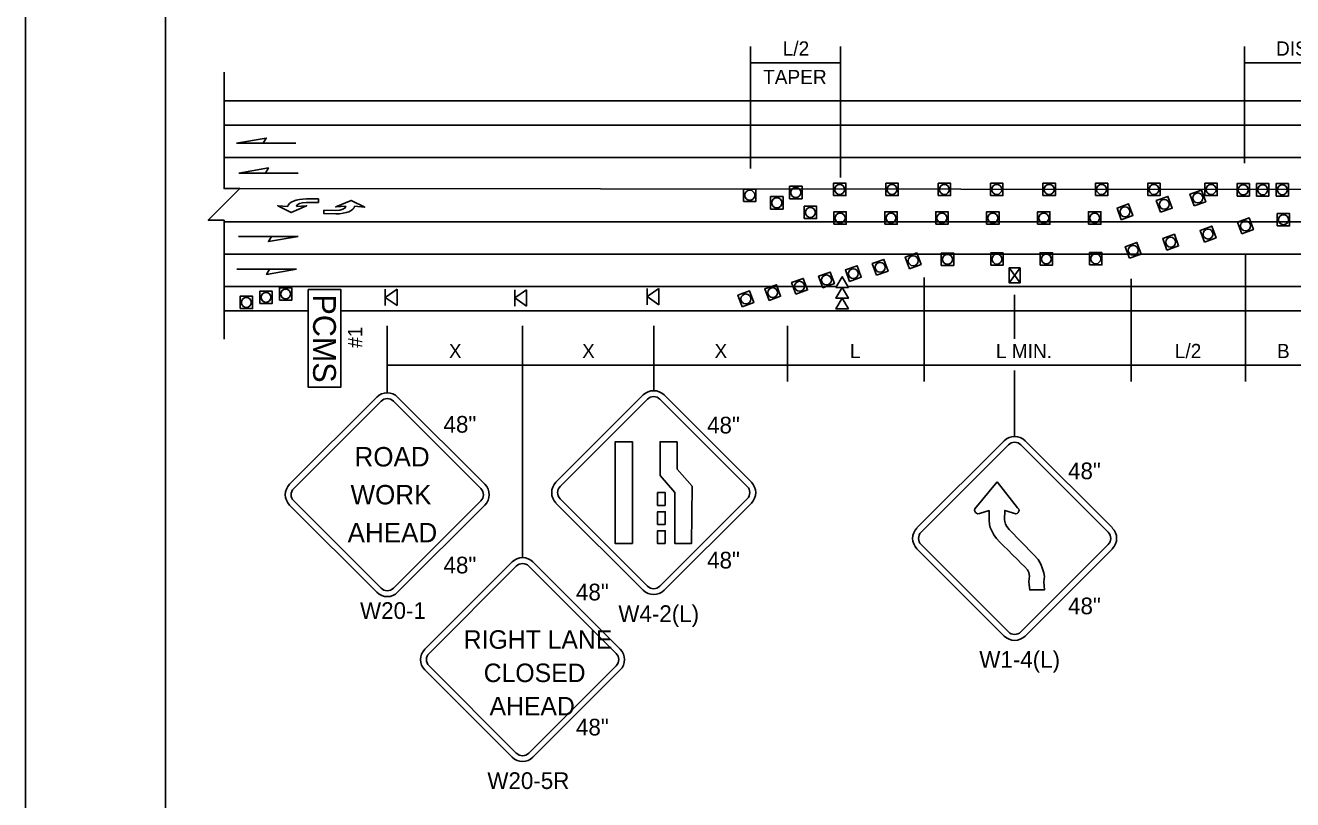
# Model space of a CAD drawing. Extents: x 99988 to 100172, y 99995 to 100047.
# Drawn here: x 99999.31 to 100005.53, y 100002.93 to 100006.73 of the extents above; entities that cross this region are included whole.
import ezdxf

# ---------------------------------------------------------------- set-up
doc = ezdxf.new("R2010")
doc.units = 0
for name, color, linetype in [('Default', 7, 'Continuous'), ('Level 15', 7, 'Continuous'), ('Level 20', 7, 'Continuous'), ('RD_MK_TrafficArrowType2LNew', 7, 'Continuous'), ('SH_GI_PlotLimits', 7, 'Continuous'), ('SH_GI_SheetBorder', 7, 'Continuous'), ('SH_GI_TrafficMvmntArrowRt1Lane', 7, 'Continuous'), ('TR_SN_WarningSigns', 7, 'Continuous'), ('TR_WZ_PortableChangeMessageSign', 7, 'Continuous'), ('TR_WZ_TrafficSafetyCone', 7, 'Continuous'), ('TR_WZ_WorkZoneDetails', 7, 'Continuous')]:
    doc.layers.add(name, color=color, linetype=linetype)

msp = doc.modelspace()

# ---------------------------------------------------------------- linework, layer by layer
at = {"layer": 'Default'}
for p, q in [((100000.2851, 100006.0802), (100006.7403, 100006.0802)), ((100010.7948, 100005.918), (100000.3647, 100005.9267)), ((100000.2916, 100005.7634), (100010.9542, 100005.7634)), ((100000.2873, 100005.6051), (100006.1821, 100005.6051)), ((100004.1939, 100005.5373), (100004.1395, 100005.4647)), ((100004.1395, 100005.5373), (100004.1939, 100005.4647)), ((100004.1667, 100005.501), (100004.1667, 100005.501)), ((100004.1668, 100005.5011), (100004.1668, 100005.5011)), ((100001.1362, 100005.433), (100001.0784, 100005.3927)), ((100001.0784, 100005.3525), (100001.0784, 100005.433)), ((100001.1362, 100005.3525), (100001.1362, 100005.433)), ((100001.7713, 100005.4308), (100001.7135, 100005.3905)), ((100001.7135, 100005.3504), (100001.7135, 100005.4308)), ((100001.7713, 100005.3504), (100001.7713, 100005.4308)), ((100002.4215, 100005.4373), (100002.3638, 100005.397)), ((100002.3638, 100005.3569), (100002.3638, 100005.4373)), ((100002.4215, 100005.3569), (100002.3638, 100005.397)), ((100002.4215, 100005.3569), (100002.4215, 100005.4373)), ((100001.1362, 100005.3525), (100001.0784, 100005.3927)), ((100001.7713, 100005.3504), (100001.7135, 100005.3905))]:
    msp.add_line(p, q, dxfattribs=at)
msp.add_lwpolyline([(100004.1939, 100005.5373), (100004.1395, 100005.5373), (100004.1395, 100005.4647), (100004.1939, 100005.4647)], close=True, dxfattribs=at)
at = {"layer": 'Level 15'}
for p, q in [((100002.8711, 100006.5446), (100003.0914, 100006.5446)), ((100003.3116, 100006.5446), (100003.0914, 100006.5446)), ((100005.295, 100006.5446), (100006.1066, 100006.5446)), ((100001.0883, 100005.0597), (100001.4203, 100005.0597)), ((100001.7522, 100005.0597), (100001.4203, 100005.0597)), ((100001.7522, 100005.0597), (100002.0739, 100005.0597)), ((100002.3955, 100005.0597), (100002.0739, 100005.0597)), ((100002.3955, 100005.0597), (100002.7237, 100005.0597)), ((100003.0518, 100005.0597), (100002.7237, 100005.0597)), ((100003.0518, 100005.0597), (100003.3873, 100005.0597)), ((100003.7229, 100005.0597), (100003.3873, 100005.0597)), ((100003.7229, 100005.0597), (100004.231, 100005.0597)), ((100004.739, 100005.0597), (100004.231, 100005.0597)), ((100004.739, 100005.0597), (100005.0192, 100005.0597)), ((100005.2994, 100005.0597), (100005.0192, 100005.0597)), ((100005.2994, 100005.0597), (100005.4876, 100005.0597)), ((100005.6757, 100005.0597), (100005.4876, 100005.0597))]:
    msp.add_line(p, q, dxfattribs=at)
at = {"layer": 'RD_MK_TrafficArrowType2LNew'}
for p, q in [((100000.6009, 100005.8387), (100000.6009, 100005.8387)), ((100000.6426, 100005.8387), (100000.6426, 100005.8387)), ((100000.6926, 100005.8762), (100000.6926, 100005.8762)), ((100000.6926, 100005.8762), (100000.6926, 100005.8762)), ((100000.6926, 100005.8595), (100000.6926, 100005.8595)), ((100000.8858, 100005.8403), (100000.8858, 100005.8403)), ((100000.9275, 100005.8399), (100000.9275, 100005.8399)), ((100000.8355, 100005.8034), (100000.8355, 100005.8034)), ((100000.8355, 100005.8034), (100000.8355, 100005.8034)), ((100000.8356, 100005.82), (100000.8356, 100005.82))]:
    msp.add_line(p, q, dxfattribs=at)
for points in [[(100000.6426, 100005.8387), (100000.6926, 100005.8429), (100000.6176, 100005.8095), (100000.5509, 100005.8429), (100000.6009, 100005.8387)], [(100000.6926, 100005.8762), (100000.7509, 100005.8762), (100000.7509, 100005.8595), (100000.6926, 100005.8595)], [(100000.8858, 100005.8403), (100000.8358, 100005.8367), (100000.9111, 100005.8693), (100000.9775, 100005.8353), (100000.9275, 100005.8399)], [(100000.8355, 100005.8034), (100000.7771, 100005.804), (100000.7773, 100005.8206), (100000.8356, 100005.82)]]:
    msp.add_lwpolyline(points, dxfattribs=at)
for centre, major_axis, ratio, start_param in [((100000.6926, 100005.8387), (-0.0917, 0), 0.40879, 4.712524), ((100000.6926, 100005.8387), (-0.05, 0), 0.41611, 4.712518), ((100000.8358, 100005.8408), (0.0917, -0.0009), 0.40879, 4.712524), ((100000.8358, 100005.8408), (0.05, -0.0005), 0.41611, 4.712518)]:
    msp.add_ellipse(centre, major_axis=major_axis, ratio=ratio, start_param=start_param, end_param=6.283185, dxfattribs=at)
at = {"layer": 'SH_GI_PlotLimits'}
msp.add_lwpolyline([(99999.3125, 99999.9375), (100015.8125, 99999.9375), (100015.8125, 100010.4375), (99999.3125, 100010.4375)], close=True, dxfattribs=at)
at = {"layer": 'SH_GI_SheetBorder'}
msp.add_line((100000, 100010.375), (100000, 100000), dxfattribs=at)
at = {"layer": 'SH_GI_TrafficMvmntArrowRt1Lane'}
for p, q in [((100000.4795, 100006.1493), (100000.6403, 100006.1493)), ((100000.4904, 100006.0023), (100000.6512, 100006.0023)), ((100000.5196, 100005.6923), (100000.3589, 100005.6923)), ((100000.5113, 100005.5312), (100000.3505, 100005.5312))]:
    msp.add_line(p, q, dxfattribs=at)
for points in [[(100000.3485, 100006.1493), (100000.4944, 100006.175), (100000.4795, 100006.1493)], [(100000.3594, 100006.0023), (100000.5053, 100006.0281), (100000.4904, 100006.0023)], [(100000.6507, 100005.6923), (100000.5048, 100005.6666), (100000.5196, 100005.6923)], [(100000.6423, 100005.5312), (100000.4964, 100005.5055), (100000.5113, 100005.5312)]]:
    msp.add_lwpolyline(points, close=True, dxfattribs=at)
at = {"layer": 'TR_SN_WarningSigns'}
for p, q in [((100000.609, 100004.4754), (100001.0373, 100004.9038)), ((100001.1393, 100004.9038), (100001.5676, 100004.4754)), ((100001.9162, 100004.4855), (100002.3445, 100004.9139)), ((100002.4465, 100004.9139), (100002.8749, 100004.4855)), ((100000.6294, 100004.455), (100001.0577, 100004.8834)), ((100001.1189, 100004.8834), (100001.5473, 100004.455)), ((100001.9366, 100004.4651), (100002.3649, 100004.8935)), ((100002.4261, 100004.8935), (100002.8545, 100004.4651)), ((100004.1156, 100004.6892), (100003.6873, 100004.2609)), ((100004.136, 100004.6688), (100003.7077, 100004.2405)), ((100004.6256, 100004.2405), (100004.1972, 100004.6688)), ((100004.646, 100004.2609), (100004.2176, 100004.6892)), ((100002.3649, 100003.9756), (100001.9366, 100004.404)), ((100002.8545, 100004.404), (100002.4261, 100003.9756)), ((100001.0373, 100003.9451), (100000.609, 100004.3734)), ((100001.0577, 100003.9655), (100000.6294, 100004.3938)), ((100001.5472, 100004.3938), (100001.1189, 100003.9655)), ((100001.5676, 100004.3734), (100001.1393, 100003.9451)), ((100002.3445, 100003.9552), (100001.9162, 100004.3836)), ((100002.8749, 100004.3836), (100002.4465, 100003.9552)), ((100003.6873, 100004.1589), (100004.1156, 100003.7306)), ((100003.7077, 100004.1793), (100004.136, 100003.7509)), ((100004.1972, 100003.7509), (100004.6256, 100004.1793)), ((100004.2176, 100003.7306), (100004.646, 100004.1589)), ((100001.2729, 100003.6659), (100001.7012, 100004.0943)), ((100001.8032, 100004.0943), (100002.2315, 100003.6659)), ((100001.2933, 100003.6455), (100001.7216, 100004.0739)), ((100001.7828, 100004.0739), (100002.2112, 100003.6455)), ((100001.7012, 100003.1356), (100001.2729, 100003.5639)), ((100001.7216, 100003.156), (100001.2933, 100003.5844)), ((100002.2112, 100003.5844), (100001.7828, 100003.156)), ((100002.2315, 100003.5639), (100001.8032, 100003.1356))]:
    msp.add_line(p, q, dxfattribs=at)
for points in [[(100002.291, 100004.1846), (100002.2071, 100004.1846), (100002.2071, 100004.6846), (100002.291, 100004.6846)], [(100002.511, 100004.6845), (100002.511, 100004.5497), (100002.584, 100004.4661), (100002.5804, 100004.1845), (100002.5, 100004.1845), (100002.5, 100004.4346), (100002.427, 100004.5182), (100002.427, 100004.6845)], [(100004.0816, 100004.4868), (100003.9709, 100004.3554), (100003.9692, 100004.3476), (100003.974, 100004.3378), (100003.9843, 100004.3305), (100003.9935, 100004.3327), (100004.0416, 100004.3467), (100004.042, 100004.299), (100004.0435, 100004.2773), (100004.0469, 100004.2634), (100004.0525, 100004.2501), (100004.0653, 100004.2275), (100004.0781, 100004.2097), (100004.0935, 100004.1914), (100004.1124, 100004.1739), (100004.1333, 100004.1532), (100004.1562, 100004.1293), (100004.1785, 100004.1077), (100004.1982, 100004.0867), (100004.2154, 100004.0712), (100004.2291, 100004.0549), (100004.2359, 100004.0419), (100004.2389, 100004.0242), (100004.2366, 100003.998), (100004.2382, 100003.9812), (100004.2405, 100003.9572), (100004.3124, 100003.9573), (100004.3102, 100003.9973), (100004.3125, 100004.0235), (100004.3095, 100004.0412), (100004.3036, 100004.0606), (100004.2957, 100004.0832), (100004.2827, 100004.107), (100004.2586, 100004.1306), (100004.1397, 100004.2539), (100004.1277, 100004.2682), (100004.1215, 100004.2789), (100004.1193, 100004.2931), (100004.1171, 100004.3023), (100004.1181, 100004.3475), (100004.1719, 100004.3305), (100004.1786, 100004.3318), (100004.1835, 100004.3366), (100004.1882, 100004.3476), (100004.1868, 100004.3534), (100004.1805, 100004.3592)], [(100002.4521, 100004.3721), (100002.415, 100004.3721), (100002.415, 100004.4346), (100002.4521, 100004.4346)], [(100002.4521, 100004.2783), (100002.415, 100004.2783), (100002.415, 100004.3408), (100002.4521, 100004.3408)], [(100002.4521, 100004.1846), (100002.415, 100004.1846), (100002.415, 100004.2471), (100002.4521, 100004.2471)]]:
    msp.add_lwpolyline(points, close=True, dxfattribs=at)
for centre, radius, start, end in [((100001.0883, 100004.8528), 0.0721, 44.99628, 134.99965), ((100002.3955, 100004.8629), 0.0721, 44.99628, 134.99965), ((100002.3955, 100004.8629), 0.0433, 44.99628, 134.99965), ((100001.0883, 100004.8528), 0.0433, 44.99628, 134.99965), ((100004.1666, 100004.6382), 0.0721, 44.99628, 134.99965), ((100004.1667, 100004.6382), 0.0433, 44.99628, 134.99965), ((100000.66, 100004.4244), 0.0721, 134.99658, 224.99358), ((100001.5167, 100004.4244), 0.0721, 314.99936, 44.99485), ((100001.9672, 100004.4346), 0.0721, 134.99658, 224.99358), ((100001.9672, 100004.4346), 0.0433, 134.99658, 224.99358), ((100002.8239, 100004.4345), 0.0433, 314.99936, 44.99485), ((100002.8239, 100004.4345), 0.0721, 314.99936, 44.99485), ((100000.66, 100004.4244), 0.0433, 134.99658, 224.99358), ((100001.5167, 100004.4244), 0.0433, 314.99936, 44.99485), ((100003.7383, 100004.2099), 0.0721, 134.99658, 224.99358), ((100003.7383, 100004.2099), 0.0433, 134.99658, 224.99358), ((100004.595, 100004.2099), 0.0433, 314.99936, 44.99485), ((100004.595, 100004.2099), 0.0721, 314.99936, 44.99485), ((100001.7522, 100004.0433), 0.0721, 44.99628, 134.99965), ((100001.7522, 100004.0433), 0.0433, 44.99628, 134.99965), ((100001.0883, 100003.9961), 0.0433, 225, 314.99958), ((100002.3955, 100004.0062), 0.0433, 225, 314.99958), ((100001.0883, 100003.9961), 0.0721, 225, 314.99958), ((100002.3955, 100004.0062), 0.0721, 225, 314.99958), ((100004.1666, 100003.7815), 0.0721, 225, 314.99958), ((100004.1666, 100003.7815), 0.0433, 225, 314.99958), ((100001.3239, 100003.6149), 0.0721, 134.99658, 224.99358), ((100002.1806, 100003.6149), 0.0721, 314.99936, 44.99485), ((100001.3239, 100003.6149), 0.0433, 134.99658, 224.99358), ((100002.1806, 100003.6149), 0.0433, 314.99936, 44.99485), ((100001.7522, 100003.1866), 0.0721, 225, 314.99958), ((100001.7522, 100003.1866), 0.0433, 225, 314.99958)]:
    msp.add_arc(centre, radius, start, end, dxfattribs=at)
at = {"layer": 'TR_WZ_PortableChangeMessageSign'}
msp.add_lwpolyline([(100000.7004, 100005.4317), (100000.7004, 100004.9517), (100000.8604, 100004.9517), (100000.8604, 100005.4317)], close=True, dxfattribs=at)
at = {"layer": 'TR_WZ_TrafficSafetyCone'}
for points in [[(100002.8367, 100005.8642), (100002.8975, 100005.8642), (100002.8975, 100005.9249), (100002.8367, 100005.9249)], [(100003.0625, 100005.8775), (100003.1233, 100005.8775), (100003.1233, 100005.9382), (100003.0625, 100005.9382)], [(100003.2777, 100005.8923), (100003.3384, 100005.8923), (100003.3384, 100005.953), (100003.2777, 100005.953)], [(100003.5347, 100005.8923), (100003.5954, 100005.8923), (100003.5954, 100005.953), (100003.5347, 100005.953)], [(100003.7917, 100005.8923), (100003.8524, 100005.8923), (100003.8524, 100005.953), (100003.7917, 100005.953)], [(100004.0487, 100005.8923), (100004.1094, 100005.8923), (100004.1094, 100005.953), (100004.0487, 100005.953)], [(100004.3057, 100005.8923), (100004.3664, 100005.8923), (100004.3664, 100005.953), (100004.3057, 100005.953)], [(100004.5627, 100005.8923), (100004.6234, 100005.8923), (100004.6234, 100005.953), (100004.5627, 100005.953)], [(100004.8197, 100005.8923), (100004.8804, 100005.8923), (100004.8804, 100005.953), (100004.8197, 100005.953)], [(100005.0473, 100005.8421), (100005.1044, 100005.8628), (100005.0836, 100005.9199), (100005.0266, 100005.8991)], [(100005.1002, 100005.8923), (100005.161, 100005.8923), (100005.161, 100005.953), (100005.1002, 100005.953)], [(100005.2577, 100005.8905), (100005.3184, 100005.8905), (100005.3184, 100005.9513), (100005.2577, 100005.9513)], [(100005.3536, 100005.8906), (100005.4143, 100005.8906), (100005.4143, 100005.9513), (100005.3536, 100005.9513)], [(100005.4495, 100005.8906), (100005.5102, 100005.8906), (100005.5102, 100005.9514), (100005.4495, 100005.9514)], [(100002.9694, 100005.8267), (100003.0302, 100005.8267), (100003.0302, 100005.8874), (100002.9694, 100005.8874)], [(100003.134, 100005.7795), (100003.1948, 100005.7795), (100003.1948, 100005.8403), (100003.134, 100005.8403)], [(100004.6897, 100005.774), (100004.7468, 100005.7948), (100004.726, 100005.8518), (100004.669, 100005.8311)], [(100004.8826, 100005.8107), (100004.9397, 100005.8315), (100004.9189, 100005.8886), (100004.8618, 100005.8678)], [(100003.2798, 100005.7523), (100003.3405, 100005.7523), (100003.3405, 100005.813), (100003.2798, 100005.813)], [(100003.5296, 100005.7523), (100003.5904, 100005.7523), (100003.5904, 100005.813), (100003.5296, 100005.813)], [(100003.7795, 100005.7522), (100003.8402, 100005.7522), (100003.8402, 100005.813), (100003.7795, 100005.813)], [(100004.0293, 100005.7522), (100004.09, 100005.7522), (100004.09, 100005.8129), (100004.0293, 100005.8129)], [(100004.2791, 100005.7522), (100004.3398, 100005.7522), (100004.3398, 100005.8129), (100004.2791, 100005.8129)], [(100004.5289, 100005.7521), (100004.5897, 100005.7521), (100004.5897, 100005.8129), (100004.5289, 100005.8129)], [(100005.2814, 100005.7048), (100005.3385, 100005.7256), (100005.3177, 100005.7827), (100005.2606, 100005.7619)], [(100005.4554, 100005.7438), (100005.5161, 100005.7438), (100005.5161, 100005.8045), (100005.4554, 100005.8045)], [(100005.0977, 100005.6648), (100005.1548, 100005.6856), (100005.134, 100005.7427), (100005.0769, 100005.7219)], [(100004.7303, 100005.5848), (100004.7873, 100005.6056), (100004.7666, 100005.6627), (100004.7095, 100005.6419)], [(100004.914, 100005.6248), (100004.971, 100005.6456), (100004.9503, 100005.7027), (100004.8932, 100005.6819)], [(100003.6508, 100005.5337), (100003.7078, 100005.5545), (100003.6871, 100005.6116), (100003.63, 100005.5908)], [(100003.8068, 100005.5495), (100003.8675, 100005.5495), (100003.8675, 100005.6102), (100003.8068, 100005.6102)], [(100004.0493, 100005.5504), (100004.11, 100005.5504), (100004.11, 100005.6111), (100004.0493, 100005.6111)], [(100004.2918, 100005.5513), (100004.3525, 100005.5513), (100004.3525, 100005.612), (100004.2918, 100005.612)], [(100004.5343, 100005.5522), (100004.5951, 100005.5522), (100004.5951, 100005.6129), (100004.5343, 100005.6129)], [(100003.3569, 100005.4706), (100003.414, 100005.4914), (100003.3932, 100005.5484), (100003.3361, 100005.5277)], [(100003.4887, 100005.5016), (100003.5458, 100005.5224), (100003.525, 100005.5795), (100003.4679, 100005.5587)], [(100003.0933, 100005.4085), (100003.1504, 100005.4293), (100003.1296, 100005.4864), (100003.0725, 100005.4656)], [(100003.2251, 100005.4396), (100003.2822, 100005.4603), (100003.2614, 100005.5174), (100003.2043, 100005.4966)], [(100000.3664, 100005.3378), (100000.4271, 100005.3378), (100000.4271, 100005.3985), (100000.3664, 100005.3985)], [(100000.4628, 100005.3625), (100000.5235, 100005.3625), (100000.5235, 100005.4232), (100000.4628, 100005.4232)], [(100000.5591, 100005.3791), (100000.6199, 100005.3791), (100000.6199, 100005.4399), (100000.5591, 100005.4399)], [(100002.8297, 100005.3464), (100002.8867, 100005.3672), (100002.866, 100005.4243), (100002.8089, 100005.4035)], [(100002.9615, 100005.3775), (100003.0186, 100005.3982), (100002.9978, 100005.4553), (100002.9407, 100005.4345)]]:
    msp.add_lwpolyline(points, close=True, dxfattribs=at)
for centre in [(100002.8671, 100005.8946), (100003.0929, 100005.9078), (100003.308, 100005.9227), (100003.565, 100005.9227), (100003.822, 100005.9227), (100004.079, 100005.9227), (100004.336, 100005.9227), (100004.5931, 100005.9227), (100004.8501, 100005.9227), (100005.0655, 100005.881), (100005.1306, 100005.9227), (100005.2881, 100005.9209), (100005.384, 100005.921), (100005.4799, 100005.921), (100002.9998, 100005.8571), (100003.1644, 100005.8099), (100004.7079, 100005.8129), (100004.9008, 100005.8496), (100003.3102, 100005.7827), (100003.56, 100005.7826), (100003.8098, 100005.7826), (100004.0596, 100005.7826), (100004.3095, 100005.7825), (100004.5593, 100005.7825), (100005.2996, 100005.7437), (100005.4858, 100005.7741), (100005.1158, 100005.7037), (100004.7484, 100005.6238), (100004.9321, 100005.6637), (100003.6689, 100005.5726), (100003.8372, 100005.5798), (100004.0797, 100005.5807), (100004.3222, 100005.5816), (100004.5647, 100005.5825), (100003.375, 100005.5095), (100003.5068, 100005.5406), (100003.1114, 100005.4474), (100003.2432, 100005.4785), (100000.4932, 100005.3929), (100000.5895, 100005.4095), (100002.8478, 100005.3854), (100002.9796, 100005.4164), (100000.3968, 100005.3681)]:
    msp.add_circle(centre, 0.0244, dxfattribs=at)
at = {"layer": 'TR_WZ_WorkZoneDetails'}
for p, q in [((100002.8711, 100006.6246), (100002.8711, 100006.0249)), ((100003.3116, 100005.9822), (100003.3116, 100006.6246)), ((100005.295, 100006.0513), (100005.295, 100006.6246)), ((100000.2873, 100006.3578), (100006.7403, 100006.3578)), ((100000.2873, 100006.2386), (100006.7403, 100006.2386)), ((100005.2994, 100005.6048), (100005.2994, 100004.9797)), ((100003.7229, 100005.4898), (100003.7229, 100004.9797)), ((100004.739, 100005.4848), (100004.739, 100004.9797)), ((100000.2873, 100005.4467), (100003.2903, 100005.4467)), ((100003.3501, 100005.4467), (100006.1821, 100005.4467)), ((100004.1667, 100005.4056), (100004.1667, 100005.1897)), ((100000.2873, 100005.3275), (100000.6998, 100005.3275)), ((100000.8604, 100005.3275), (100006.7403, 100005.3275)), ((100001.0883, 100005.2525), (100001.0883, 100004.9249)), ((100001.7522, 100005.2525), (100001.7522, 100004.1154)), ((100002.3955, 100005.2525), (100002.3955, 100004.935)), ((100003.0518, 100005.2525), (100003.0518, 100004.9797)), ((100004.1667, 100005.0347), (100004.1667, 100004.7103))]:
    msp.add_line(p, q, dxfattribs=at)
msp.add_lwpolyline([(100000.2873, 100006.4978), (100000.2873, 100005.9267), (100000.3647, 100005.9267), (100000.2099, 100005.7718), (100000.2873, 100005.7718), (100000.2873, 100005.1875)], dxfattribs=at)
msp.add_lwpolyline([(100003.351, 100005.3363), (100003.2899, 100005.3363), (100003.3204, 100005.3891), (100003.2899, 100005.3891), (100003.3204, 100005.4418), (100003.2899, 100005.4418), (100003.3204, 100005.4946), (100003.351, 100005.4418), (100003.3204, 100005.4418), (100003.351, 100005.3891), (100003.3204, 100005.3891)], close=True, dxfattribs=at)

# ---------------------------------------------------------------- texts
at = {"layer": 'Level 20'}
for s, p in [('L/2', (100003.0286, 100006.5796)), ('DISTANCE FOR OPPOSING', (100005.449, 100006.5796)), ('TAPER', (100002.9324, 100006.4396)), ('X', (100002.6939, 100005.0947)), ('L', (100003.3583, 100005.0947)), ('L MIN.', (100004.0745, 100005.0947)), ('L/2', (100004.9525, 100005.0947)), ('B', (100005.4539, 100005.0947))]:
    msp.add_text(s, height=0.07, dxfattribs=at).set_placement(p)
for s, rotation, p in [('#1', 90, (100000.9654, 100005.1454)), ('X', 360, (100001.3906, 100005.0947)), ('X', 360, (100002.0442, 100005.0947))]:
    msp.add_text(s, height=0.07, rotation=rotation, dxfattribs=at).set_placement(p)
at = {"layer": 'TR_SN_WarningSigns'}
for s, height, p in [('48"', 0.08203, (100001.3644, 100004.7289)), ('48"', 0.08203, (100002.6576, 100004.725)), ('ROAD', 0.0954, (100000.9278, 100004.563)), ('48"', 0.08203, (100004.4287, 100004.5003)), ('WORK', 0.0954, (100000.9081, 100004.3768)), ('AHEAD', 0.0954, (100000.8938, 100004.1905)), ('48"', 0.08203, (100001.3644, 100004.0379)), ('48"', 0.08203, (100002.6576, 100004.0621)), ('48"', 0.08203, (100002.0143, 100003.9054)), ('48"', 0.08203, (100004.4287, 100003.8374)), ('W20-1', 0.08203, (100000.9548, 100003.8144)), ('W4-2(L)', 0.08203, (100002.2222, 100003.7993)), ('RIGHT LANE', 0.09085, (100001.4636, 100003.668)), ('W1-4(L)', 0.08203, (100003.9933, 100003.5747)), ('CLOSED', 0.09085, (100001.5616, 100003.5045)), ('AHEAD', 0.09085, (100001.5901, 100003.341)), ('48"', 0.08203, (100002.0143, 100003.2425)), ('W20-5R', 0.08203, (100001.5795, 100002.9797))]:
    msp.add_text(s, height=height, dxfattribs=at).set_placement(p)
at = {"layer": 'TR_WZ_PortableChangeMessageSign'}
msp.add_text('PCMS', height=0.112, rotation=270, dxfattribs=at).set_placement((100000.7244, 100005.4072))

doc.saveas('drawing.dxf')
